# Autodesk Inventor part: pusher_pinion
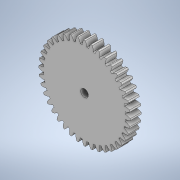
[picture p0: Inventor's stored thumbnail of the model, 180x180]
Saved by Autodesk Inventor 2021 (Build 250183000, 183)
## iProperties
Company: meta-matic.com
Created: 2026-10
Part Number: pusher_pinion
Material: Generic
Description: Spur Gear - meta-matic-generator 1.3
Document SubType Name: Modeling
Designer: alolo
Authority: META-MATIC-ID: 1c046b0d7dfa
Density: 1 g/cm^3
Appearance: Default
Sending System: Open CASCADE
Preprocessor: meta-matic-generator 1.3
Title: Spur Gear_1c046b0d7dfa
Author: Takahashi Mizuki @tkhsmz
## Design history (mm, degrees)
feature "Base1"
sketch "Sketch1"
  geometry: C1 r 3.5 at (-39.822, -0.385); 1 further point
  constraints: 1 centre point, 1 coincident
  dimensions: "d0" = 7 diameter of C1
extrude "Extrusion1" cut sketch "Sketch1" stored distance "d1" = 10; taper "d2" = 0 deg
body "Solid1"
